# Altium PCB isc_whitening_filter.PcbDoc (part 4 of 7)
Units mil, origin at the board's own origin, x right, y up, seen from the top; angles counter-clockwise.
Board outline 8440 x 7000 mil, 6 copper layers (Top Layer, MidLayer1, InternalPlane1, Internal Plane 3, InternalPlane2, Bottom Layer); 550 components, 434 nets, 2189 pads, 806 vias.
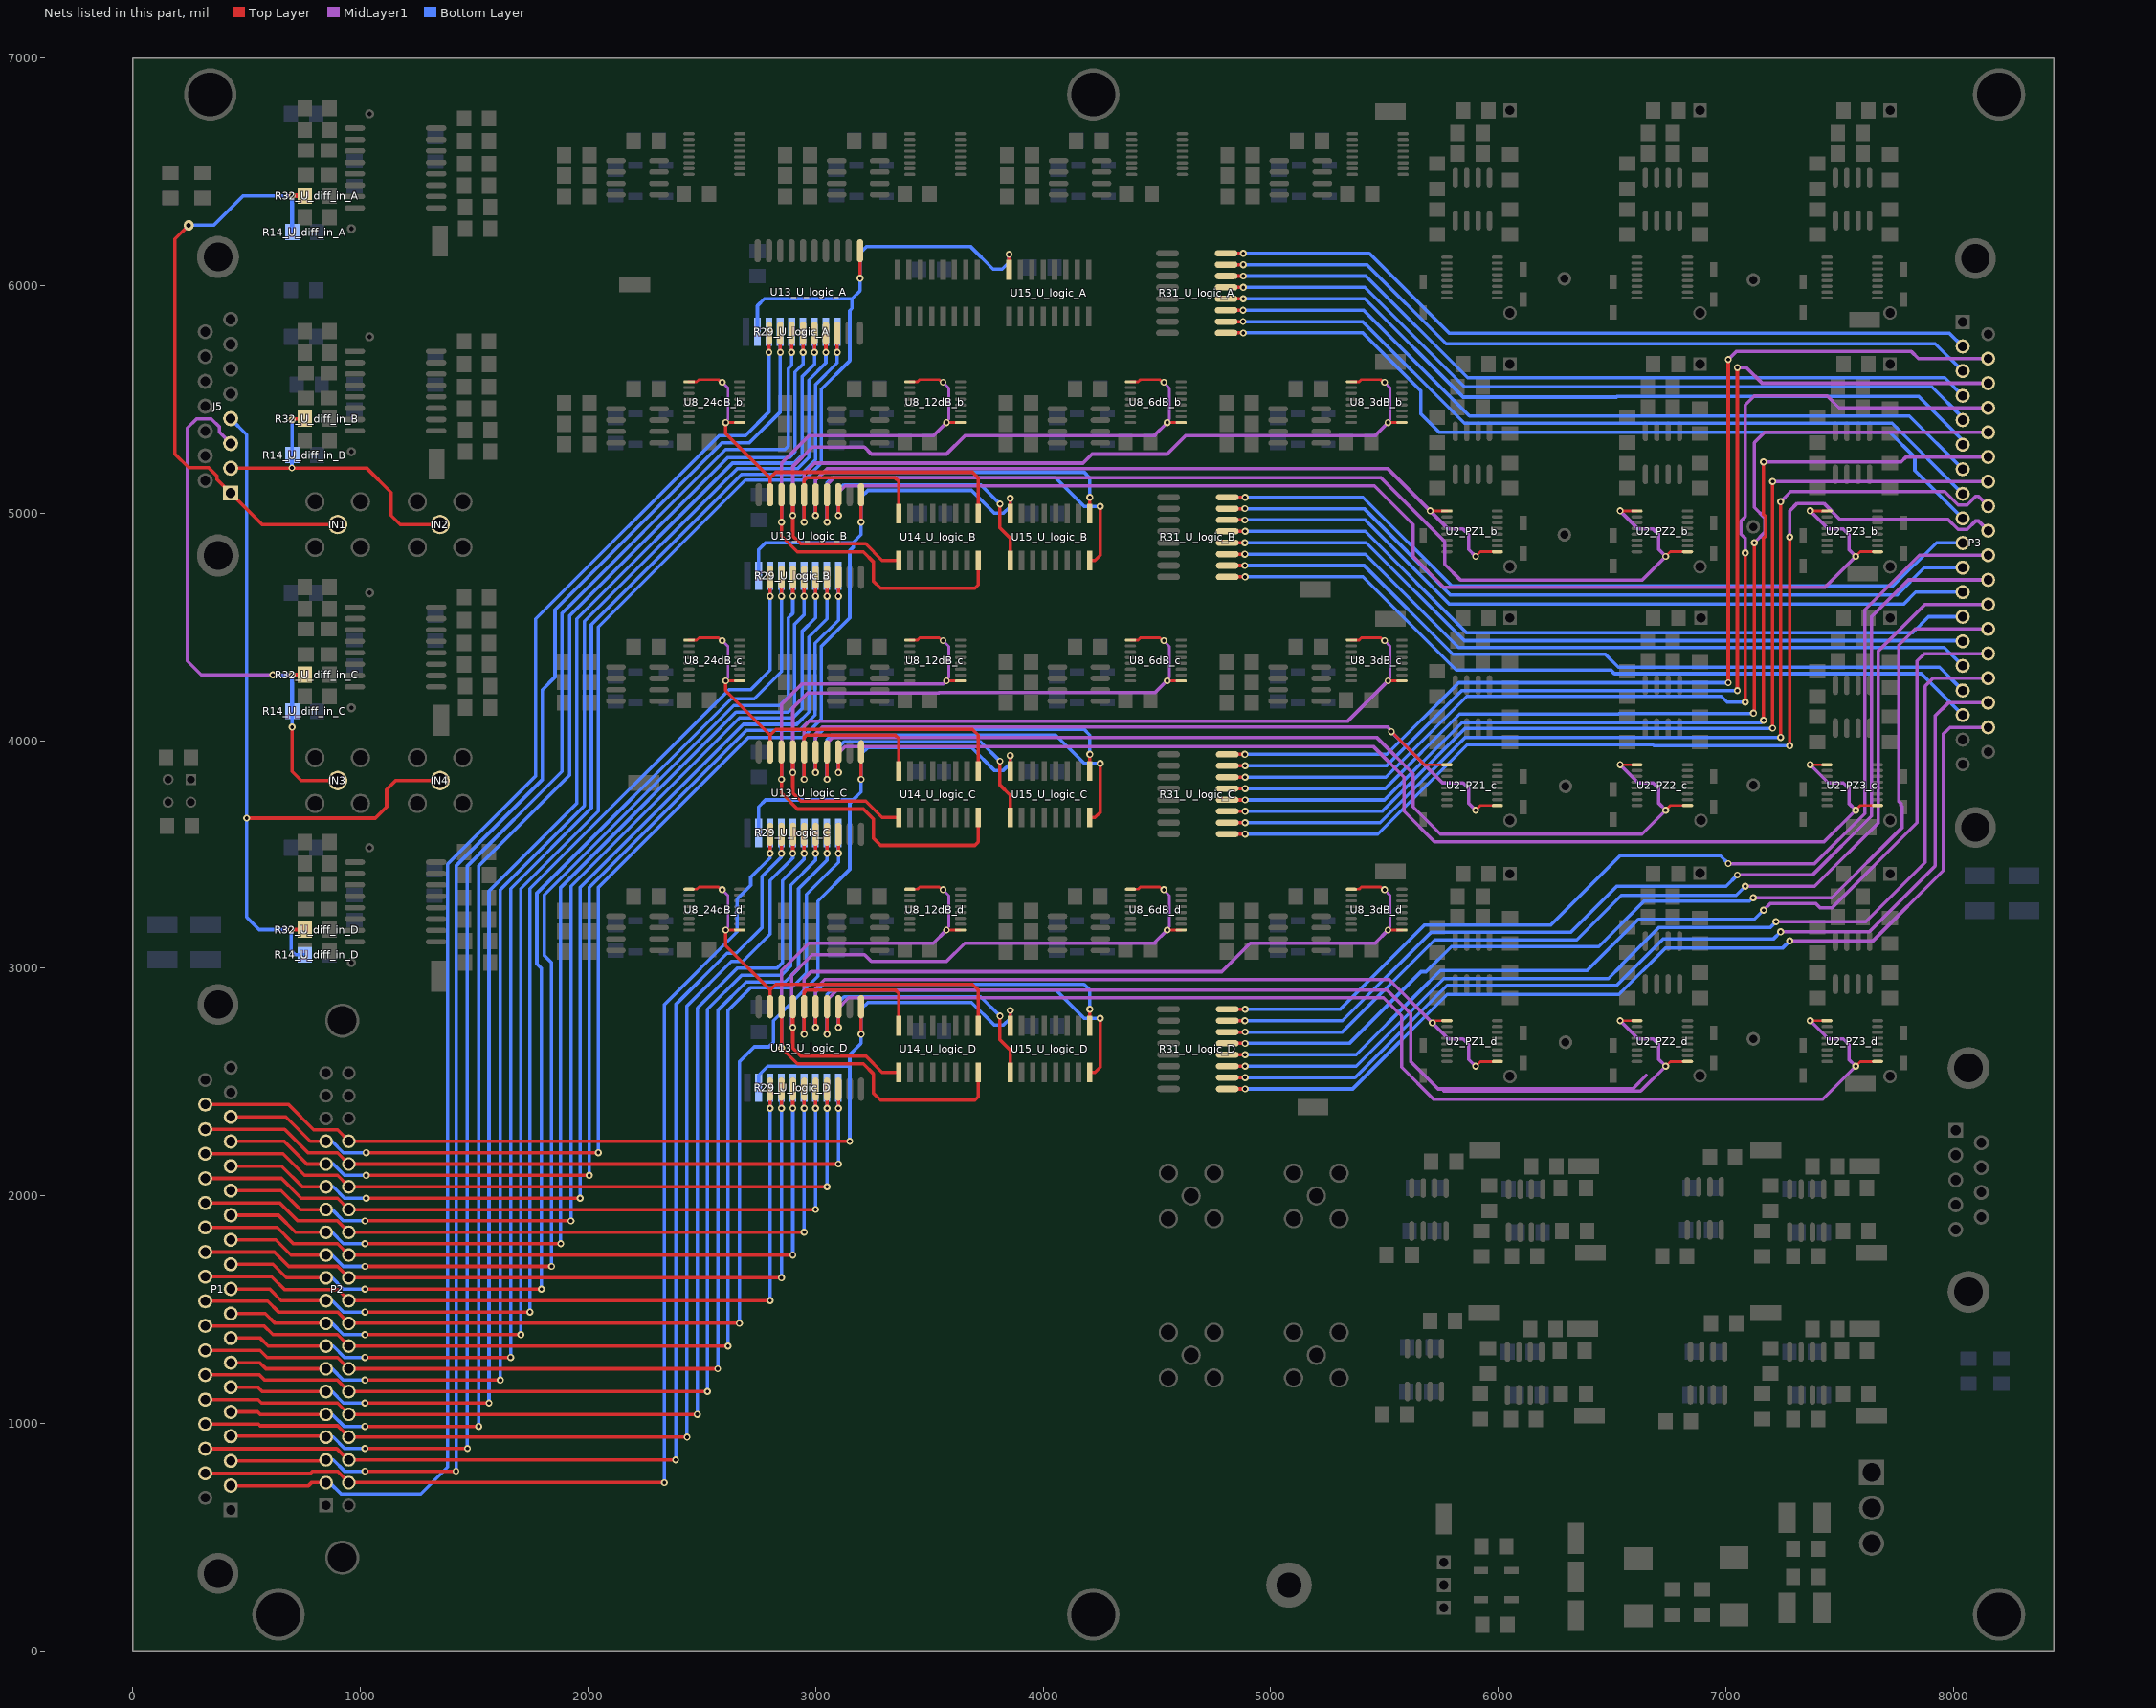
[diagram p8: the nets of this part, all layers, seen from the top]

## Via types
v1: diameter 31, hole 16, Top Layer to Bottom Layer, 805 vias
v2: diameter 45, hole 20, Top Layer to Bottom Layer, 1 vias

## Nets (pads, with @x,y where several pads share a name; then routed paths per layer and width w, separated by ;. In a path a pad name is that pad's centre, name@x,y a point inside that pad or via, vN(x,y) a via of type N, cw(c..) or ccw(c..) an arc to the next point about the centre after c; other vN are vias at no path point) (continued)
AP_1: IN1.1 J5.1 R14_U_diff_in_A.2 R32_U_diff_in_A.2 | length 2605.4
  Top Layer w15: v2(245,6265) 185,6205 185,5260 245,5200 332.74,5200 368.88,5163.86 368.88,5149.35 J5.1@429.92,5088.31 568.23,4950 IN1.1@900,4950
  Top Layer w20: v1(700,6395) R32_U_diff_in_A.2@754.88,6395
  Bottom Layer w15: v2(245,6265) 355,6265 485,6395 v1(700,6395)
  Bottom Layer w20: R14_U_diff_in_A.2@700,6235.12 v1(700,6395)
AP_2: IN2.1 J5.2 R14_U_diff_in_B.2 R32_U_diff_in_B.2 | length 1351
  Top Layer w15: J5.2@429.92,5197.36 697.36,5197.36 v1(698.68,5198.68) 1026.32,5198.68 1135,5090 1135,4990 1175,4950 IN2.1@1350,4950 ; v1(700,5410) 705,5415 R32_U_diff_in_B.2@754.88,5415
  Bottom Layer w15: v1(698.68,5198.68) 698.68,5253.68 700,5255 v1(700,5410)
AP_3: IN3.1 J5.3 R14_U_diff_in_C.2 R32_U_diff_in_C.2 | length 2471.6
  Top Layer w15: v1(700,4060) 700,3865 740,3825 IN3.1@900,3825
  Top Layer w20: v1(700,4290) R32_U_diff_in_C.2@754.88,4290
  MidLayer1 w15: J5.3@429.92,5306.42 380,5356.34 380,5380 345,5415 280,5415 240,5375 240,4350 300,4290 v1(615,4290)
  Bottom Layer w15: v1(615,4290) v1(700,4290) ; R14_U_diff_in_C.2@699.88,4130 700,4129.88 v1(700,4060)
  Bottom Layer w20: R14_U_diff_in_C.2@700,4130.12 v1(700,4290)
AP_4: IN4.1 J5.4 R14_U_diff_in_D.2 R32_U_diff_in_D.2 | length 3617.6
  Top Layer w15: v1(500,3660) 1065,3660 1115,3710 1115,3785 1155,3825 IN4.1@1350,3825 ; v1(695,3170) R32_U_diff_in_D.2@754.88,3170
  Bottom Layer w15: J5.4@429.92,5415.47 500,5345.39 v1(500,3660) 500,3225 555,3170 v1(695,3170) 695,3080 715,3060 R14_U_diff_in_D.2@754.88,3060
B1: U8_24dB_b.1 U8_24dB_b.9 U13_U_logic_B.19 U14_U_logic_B.1 | length 1898.9
  Top Layer w12: U8_24dB_b.9@2443.78,5577.36 2443.95,5577.53 2477.87,5577.53 2487.34,5587 2572.86,5587 2584.86,5575 v1(2590,5575) ; v1(2605,5398.23) U8_24dB_b.1@2666.22,5398.23
  Top Layer w15: v1(2605,5398.23) 2605,5350 2800,5155 ; U13_U_logic_B.19@2800,5081.1 2800,5155 ; U14_U_logic_B.1@3715,4997.36 3715,5155 3690,5180 2825,5180 2800,5155
  MidLayer1 w12: v1(2590,5575) 2615,5550 2615,5413.37 2605,5403.37 v1(2605,5398.23)
B2: U8_12dB_b.1 U8_12dB_b.9 U13_U_logic_B.18 U14_U_logic_B.16 | length 2771.5
  Top Layer w12: U8_12dB_b.9@3413.78,5577.36 3413.95,5577.53 3447.87,5577.53 3457.34,5587 3542.86,5587 3554.86,5575 v1(3560,5575) ; v1(3575,5398.23) U8_12dB_b.1@3636.22,5398.23
  Top Layer w15: U13_U_logic_B.18@2850,5081.1 v1(2850,4960) 2850,4900 2920,4830 3210,4830 3255,4785 3255,4700 3285,4670 3700,4670 3715,4685 U14_U_logic_B.16@3715,4792.64
  MidLayer1 w12: v1(3560,5575) 3585,5550 3585,5413.37 3575,5403.37 v1(3575,5398.23)
  MidLayer1 w15: v1(2850,4960) 2850,5220 2897.5,5267.5 2970,5340 3516.77,5340 v1(3575,5398.23)
B3: U8_6dB_b.1 U8_6dB_b.9 U13_U_logic_B.17 U14_U_logic_B.9 | length 3614.9
  Top Layer w12: U8_6dB_b.9@4383.78,5577.36 4383.95,5577.53 4417.87,5577.53 4427.34,5587 4512.86,5587 4524.86,5575 v1(4530,5575) ; v1(4545,5398.23) U8_6dB_b.1@4606.22,5398.23
  Top Layer w15: U13_U_logic_B.17@2900,5081.1 v1(2900,4990) 2900,4900 2935,4865 3220,4865 3292.36,4792.64 U14_U_logic_B.9@3365,4792.64
  MidLayer1 w12: v1(4530,5575) 4555,5550 4555,5413.37 4545,5403.37 v1(4545,5398.23)
  MidLayer1 w15: v1(2900,4990) 2900,5205 2985,5290 3215,5290 3245,5260 3575,5260 3655,5340 4491.77,5340 ; 3940,5340 4486.77,5340 v1(4545,5398.23)
B4: U8_3dB_b.1 U8_3dB_b.9 U13_U_logic_B.16 U14_U_logic_B.8 | length 4584.9
  Top Layer w12: U8_3dB_b.9@5353.78,5577.36 5353.95,5577.53 5387.87,5577.53 5397.34,5587 5482.86,5587 5494.86,5575 v1(5500,5575) ; v1(5515,5398.23) U8_3dB_b.1@5576.22,5398.23
  Top Layer w15: v1(2950,4960) U13_U_logic_B.16@2950,5081.1 2950,5145 2960,5155 3350,5155 3365,5140 U14_U_logic_B.8@3365,4997.36
  MidLayer1 w12: v1(5500,5575) 5525,5550 5525,5413.37 5515,5403.37 v1(5515,5398.23)
  MidLayer1 w15: v1(2950,4960) 2950,5175 2995,5220 4175,5220 4215,5260 4545,5260 4625,5340 5456.77,5340 ; 4910,5340 5456.77,5340 ; 5461.77,5340 5456.77,5340 ; v1(5515,5398.23) 5456.77,5340
B5: U2_PZ1_b.1 U2_PZ1_b.9 U13_U_logic_B.15 U15_U_logic_B.1 | length 5085.5
  Top Layer w12: v1(5700,5010) 5700.43,5009.57 U2_PZ1_b.1@5773.78,5009.57 ; v1(5900,4810) 5920.43,4830.43 U2_PZ1_b.9@5996.22,4830.43
  Top Layer w15: v1(3000,4990) U13_U_logic_B.15@3000,5081.1 ; U15_U_logic_B.1@4205,4997.36 v1(4205,5070)
  MidLayer1 w15: v1(3000,4990) 3000,5145 3050,5195 5515,5195 v1(5700,5010) 5780,4930 5845,4930 5870,4905 5870,4840 v1(5900,4810)
  Bottom Layer w15: v1(3000,4990) 3000,5145 3035,5180 4180,5180 4205,5155 v1(4205,5070)
B6: U2_PZ2_b.1 U2_PZ2_b.9 U13_U_logic_B.14 U15_U_logic_B.16 | length 6475.9
  Top Layer w12: v1(6535,5010) 6535.43,5009.57 U2_PZ2_b.1@6608.78,5009.57 ; v1(6735,4810) 6755.43,4830.43 U2_PZ2_b.9@6831.22,4830.43
  Top Layer w15: v1(3050,4960) U13_U_logic_B.14@3050,5081.1 ; U15_U_logic_B.16@4205,4792.64 4227.64,4792.64 4250,4815 v1(4250,5030)
  MidLayer1 w15: v1(3050,4960) 3050,5125 3080,5155 5485,5155 5765,4875 5765,4775 5835,4705 6630,4705 v1(6735,4810) 6705,4840 6705,4905 6680,4930 6615,4930 v1(6535,5010)
  Bottom Layer w15: v1(3050,4960) 3050,5135 3070,5155 4055,5155 4180,5030 v1(4250,5030)
B7: U2_PZ3_b.1 U2_PZ3_b.9 U13_U_logic_B.13 U15_U_logic_B.9 | length 6626.9
  Top Layer w12: v1(7370,5010) 7370.43,5009.57 U2_PZ3_b.1@7443.78,5009.57 ; v1(7570,4810) 7590.43,4830.43 U2_PZ3_b.9@7666.22,4830.43
  Top Layer w15: v1(3100,4990) U13_U_logic_B.13@3100,5081.1 ; v1(3810,5040) 3810,4935 3855,4890 U15_U_logic_B.9@3855,4792.64
  MidLayer1 w15: v1(3100,4990) 3100,5090 3130,5120 5455,5120 5625,4950 5625,4810 5760,4675 7380,4675 7435,4675 v1(7570,4810) 7540,4840 7540,4905 7515,4930 7450,4930 v1(7370,5010)
  Bottom Layer w15: v1(3100,4990) 3100,5100 3125,5125 3725,5125 v1(3810,5040)
BI_0: P1.2 P2.3 R29_U_logic_A.3 U13_U_logic_A.2 | length 6752.5
  Top Layer w15: P1.2@430,727 772,727 785,740 P2.3@849,740 ; v1(2795,5707) U13_U_logic_A.2@2795,5790.9
  Bottom Layer w15: P2.3@849,740 865,740 915,690 1265,690 1382.93,807.93 1382.93,3457.93 1770,3845 1770,4535 2575,5340 2690,5340 2795,5445 v1(2795,5707) ; v1@2794.41,5707.59 R29_U_logic_A.3@2794.41,5797
BI_1: P1.3 P2.5 R29_U_logic_A.4 U13_U_logic_A.3 | length 6763.6
  Top Layer w15: P1.3@430,835 844,835 P2.5@849,840 ; v1(1020,790) v1(1420,790) ; v1(2845,5707) U13_U_logic_A.3@2845,5790.9
  Bottom Layer w15: P2.5@849,840 880,840 930,790 v1(1020,790) ; v1(1420,790) 1420,3450 1800,3830 1800,4225 1855,4280 1855,4575 2590,5310 2710,5310 2845,5445 v1(2845,5707) ; v1@2844.41,5707.59 R29_U_logic_A.4@2844.41,5797
BI_2: P1.4 P2.7 R29_U_logic_A.5 U13_U_logic_A.4 | length 6795.2
  Top Layer w15: P1.4@430,944 845,944 P2.7@849,940 ; v1(1020,890) v1(1470,890) ; v1(2895,5707) U13_U_logic_A.4@2895,5790.9
  Bottom Layer w15: P2.7@849,940 880,940 930,890 v1(1020,890) ; v1(1470,890) 1470,3450 1885,3865 1885,4560 2605,5280 2865,5280 2880,5295 2880,5635 2895,5650 v1(2895,5707) ; v1@2894.41,5707.59 R29_U_logic_A.5@2894.41,5797
BI_3: P1.5 P2.9 R29_U_logic_A.6 U13_U_logic_A.5 | length 6757.5
  Top Layer w15: P1.5@430,1051 549,1051 560,1040 P2.9@849,1040 ; v1(1020,987.5) v1(1520,987.5) ; v1(2945,5707) U13_U_logic_A.5@2945,5790.9
  Bottom Layer w15: P2.9@849,1040 875,1040 927.5,987.5 v1(1020,987.5) ; v1(1520,987.5) 1520,3450 1920,3850 1920,4550 2615,5245 2885,5245 2910,5270 2910,5620 2945,5655 v1(2945,5707) ; v1@2944.41,5707.59 R29_U_logic_A.6@2944.41,5797
BI_4: P1.6 P2.11 R29_U_logic_A.7 U13_U_logic_A.6 | length 6704.4
  Top Layer w15: P1.6@430,1159 549,1159 568,1140 P2.11@849,1140 ; v1(1020,1090) v1(1565,1090) ; v1(2995,5707) U13_U_logic_A.6@2995,5790.9
  Bottom Layer w15: P2.11@849,1140 875,1140 925,1090 v1(1020,1090) ; v1(1565,1090) 1565,3340 1950,3725 1950,4535 2635,5220 2905,5220 2940,5255 2940,5600 2995,5655 v1(2995,5707) ; v1@2994.41,5707.59 R29_U_logic_A.7@2994.41,5797
BI_5: P1.7 P2.13 R29_U_logic_A.8 U13_U_logic_A.7 | length 6654.8
  Top Layer w15: P1.7@430,1267 558,1267 585,1240 P2.13@849,1240 ; v1(1020,1190) v1(1615,1190) ; v1(3045,5707) U13_U_logic_A.7@3045,5790.9
  Bottom Layer w15: P2.13@849,1240 875,1240 925,1190 v1(1020,1190) ; v1(1615,1190) 1615,3345 1984.82,3714.82 1984.82,4524.82 2655,5195 2920,5195 2970,5245 2970,5585 3045,5660 v1(3045,5707) ; v1@3044.41,5707.59 R29_U_logic_A.8@3044.41,5797
BI_6: P1.8 P2.15 R29_U_logic_A.9 U13_U_logic_A.8 | length 6602.2
  Top Layer w15: P1.8@430,1375 560,1375 595,1340 P2.15@849,1340 ; v1(1020,1290) v1(1660,1290) ; v1(3095,5707) U13_U_logic_A.8@3095,5790.9
  Bottom Layer w15: P2.15@849,1340 880,1340 930,1290 v1(1020,1290) ; v1(1660,1290) 1660,3350 2014.82,3704.82 2014.82,4509.82 2675,5170 2935,5170 3000,5235 3000,5565 3095,5660 v1(3095,5707) ; v1@3094.41,5707.59 R29_U_logic_A.9@3094.41,5797
BI_7: P1.9 P2.17 R29_U_logic_A.2 U13_U_logic_A.11 U15_U_logic_A.8 | length 8322.7
  Top Layer w15: P1.9@430,1483 582,1483 625,1440 P2.17@849,1440 ; v1(1020,1390) v1(1705,1390) ; v1(3195,6032) U13_U_logic_A.11@3195,6153.1 ; U15_U_logic_A.8@3850,6069.36 v1(3850,6137)
  Bottom Layer w15: P2.17@849,1440 875,1440 925,1390 v1(1020,1390) ; v1(1705,1390) 1705,3350 2045,3690 2045,4500 2690,5145 2950,5145 3025,5220 3025,5545 3150,5670 3150,5890 3160,5900 3160,5942 ; R29_U_logic_A.2@2744.41,5797 2744.41,5911.41 2775,5942 3160,5942 ; v1(3850,6137) 3850,6102 3820,6072 3780,6072 3680,6172 3225,6172 3195,6142 v1(3195,6032) 3195,5977 3160,5942
BI_8: P1.10 P2.19 R29_U_logic_B.3 U13_U_logic_B.2 | length 5167.8
  Top Layer w15: P1.10@430,1591 601,1591 652,1540 P2.19@849,1540 ; v1(1020,1490) v1(1745,1490) ; v1(2800,4635) U13_U_logic_B.2@2800,4718.9
  Bottom Layer w15: P2.19@849,1540 875,1540 925,1490 v1(1020,1490) ; v1(1745,1490) 1745,3350 2620,4225 2715,4225 2800,4310 v1(2800,4635) ; v1@2799.41,4635.59 R29_U_logic_B.3@2799.41,4725
BI_9: P1.11 P2.21 R29_U_logic_B.4 U13_U_logic_B.3 | length 5140.6
  Top Layer w15: P1.11@430,1699 616,1699 675,1640 P2.21@849,1640 ; v1(1020,1590) v1(1795,1590) ; v1(2850,4635) U13_U_logic_B.3@2850,4718.9
  Bottom Layer w15: P2.21@849,1640 875,1640 925,1590 v1(1020,1590) ; v1(1795,1590) 1795,3000 1775,3020 1775,3330 2630,4185 2730,4185 2850,4305 v1(2850,4635) ; v1@2849.41,4635.59 R29_U_logic_B.4@2849.41,4725
BI_10: P1.12 P2.23 R29_U_logic_B.5 U13_U_logic_B.4 | length 5162.1
  Top Layer w15: P1.12@430,1807 628,1807 695,1740 P2.23@849,1740 ; v1(1020,1690) v1(1840,1690) ; v1(2900,4635) U13_U_logic_B.4@2900,4718.9
  Bottom Layer w15: P2.23@849,1740 875,1740 925,1690 v1(1020,1690) ; v1(1840,1690) 1840,3023.33 1807,3056.33 1807,3322 2640,4155 2843,4155 2880,4192 2880,4540 2900,4560 v1(2900,4635) ; v1@2899.41,4635.59 R29_U_logic_B.5@2899.41,4725
BI_11: P1.13 P2.25 R29_U_logic_B.6 U13_U_logic_B.5 | length 5098
  Top Layer w15: P1.13@430,1915 640,1915 715,1840 P2.25@849,1840 ; v1(1020,1790) v1(1880,1790) ; v1(2950,4635) U13_U_logic_B.5@2950,4718.9
  Bottom Layer w15: P2.25@849,1840 875,1840 925,1790 v1(1020,1790) ; v1(1880,1790) 1880,3355 2650,4125 2880,4125 2908,4153 2908,4513 2950,4555 v1(2950,4635) ; v1@2949.41,4635.59 R29_U_logic_B.6@2949.41,4725
BI_12: P1.14 P2.27 R29_U_logic_B.7 U13_U_logic_B.6 | length 5051.3
  Top Layer w15: P1.14@430,2023 652,2023 735,1940 P2.27@849,1940 ; v1(1020,1890) v1(1925,1890) ; v1(3000,4635) U13_U_logic_B.6@3000,4718.9
  Bottom Layer w15: P2.27@849,1940 875,1940 925,1890 v1(1020,1890) ; v1(1925,1890) 1925,3360 2665,4100 2900,4100 2940,4140 2940,4480 3000,4540 v1(3000,4635) ; v1@2999.41,4635.59 R29_U_logic_B.7@2999.41,4725
BI_13: P1.15 P2.29 R29_U_logic_B.8 U13_U_logic_B.7 | length 4998.8
  Top Layer w15: P1.15@430,2131 654,2131 745,2040 P2.29@849,2040 ; v1(1025,1990) v1(1965,1990) ; v1(3050,4635) U13_U_logic_B.7@3050,4718.9
  Bottom Layer w15: P2.29@849,2040 880,2040 930,1990 v1(1025,1990) ; v1(1965,1990) 1965,3355 2682,4072 2917,4072 2971,4126 2971,4456 3050,4535 v1(3050,4635) ; v1@3049.41,4635.59 R29_U_logic_B.8@3049.41,4725
BI_14: P1.16 P2.31 R29_U_logic_B.9 U13_U_logic_B.8 | length 4951
  Top Layer w15: P1.16@430,2239 666,2239 765,2140 P2.31@849,2140 ; v1(1025,2090) v1(2005,2090) ; v1(3100,4635) U13_U_logic_B.8@3100,4718.9
  Bottom Layer w15: P2.31@849,2140 880,2140 930,2090 v1(1025,2090) ; v1@2005,2085 2005,3355 2695,4045 2929.64,4045 2998,4113.36 2998,4428 3100,4530 v1(3100,4635) ; v1@3099.41,4635.59 R29_U_logic_B.9@3099.41,4725
BI_15: P1.17 P2.33 R29_U_logic_B.2 U13_U_logic_B.11 U15_U_logic_B.8 | length 6666.7
  Top Layer w15: P1.17@430,2347 673,2347 780,2240 P2.33@849,2240 ; v1(1025,2190) v1(2045,2190) ; v1(3200,4960) U13_U_logic_B.11@3200,5081.1 ; U15_U_logic_B.8@3855,4997.36 v1(3855,5065)
  Bottom Layer w15: P2.33@849,2240 875,2240 925,2190 v1(1025,2190) ; v1(2045,2190) 2045,3355 2705,4015 2945,4015 3025,4095 3025,4415 3150,4540 3150,4835 3165,4850 3165,4870 ; R29_U_logic_B.2@2749.41,4725 2749.41,4839.41 2780,4870 3165,4870 ; v1(3855,5065) 3855,5030 3825,5000 3785,5000 3685,5100 3230,5100 3200,5070 v1(3200,4960) 3200,4905 3165,4870
BI_16: P1.21 P2.4 R29_U_logic_C.3 U13_U_logic_C.2 | length 5172.4
  Top Layer w15: P1.21@318,781 781,781 790,790 899,790 P2.4@949,740 v1(2335,740) ; v1(2800,3505) U13_U_logic_C.2@2800,3588.9
  Bottom Layer w15: v1(2335,740) 2335,2840 2655,3160 2655,3305 2715,3365 2715,3400 2800,3485 v1(2800,3505) ; v1@2799.41,3505.59 R29_U_logic_C.3@2799.41,3595
BI_17: P1.22 P2.6 R29_U_logic_C.4 U13_U_logic_C.3 | length 5141.6
  Top Layer w15: P1.22@318,889 896,889 945,840 P2.6@949,840 v1(2385,840) ; v1(2850,3505) U13_U_logic_C.3@2850,3588.9
  Bottom Layer w15: v1(2385,840) 2385,2840 2611.33,3066.33 2651.33,3066.33 2765,3180 2765,3405 2850,3490 v1(2850,3505) ; v1@2849.41,3505.59 R29_U_logic_C.4@2849.41,3595
BI_18: P1.23 P2.8 R29_U_logic_C.5 U13_U_logic_C.4 | length 5100.8
  Top Layer w15: P1.23@318,997 553,997 560,990 899,990 P2.8@949,940 v1(2435,940) ; v1(2900,3505) U13_U_logic_C.4@2900,3588.9
  Bottom Layer w15: v1(2435,940) 2435,2835 2630,3030 2680,3030 2800,3150 2800,3385 2900,3485 v1(2900,3505) ; v1@2899.41,3505.59 R29_U_logic_C.5@2899.41,3595
BI_19: P1.24 P2.10 R29_U_logic_C.6 U13_U_logic_C.5 | length 5125
  Top Layer w15: P1.24@318,1105 550,1105 565,1090 900,1090 949,1041 P2.10@949,1040 v1(2480,1040) ; v1(2950,3505) U13_U_logic_C.5@2950,3588.9
  Bottom Layer w15: v1(2480,1040) 2480,2825 2655,3000 2830,3000 2855,3025 2855,3385 2950,3480 v1(2950,3505) ; v1@2949.41,3505.59 R29_U_logic_C.6@2949.41,3595
BI_20: P1.25 P2.12 R29_U_logic_C.7 U13_U_logic_C.6 | length 5074.8
  Top Layer w15: P1.25@318,1213 557,1213 580,1190 899,1190 P2.12@949,1140 v1(2525,1140) ; v1(3000,3505) U13_U_logic_C.6@3000,3588.9
  Bottom Layer w15: v1(2525,1140) 2525,2820 2675,2970 2850,2970 2890,3010 2890,3365 3000,3475 v1(3000,3505) ; v1@2999.41,3505.59 R29_U_logic_C.7@2999.41,3595
BI_21: P1.26 P2.14 R29_U_logic_C.8 U13_U_logic_C.7 | length 5022.3
  Top Layer w15: P1.26@318,1321 559,1321 590,1290 899,1290 P2.14@949,1240 v1(2570,1240) ; v1(3050,3505) U13_U_logic_C.7@3050,3588.9
  Bottom Layer w15: v1(2570,1240) 2570,2815 2695,2940 2865,2940 2925,3000 2925,3350 3050,3475 v1(3050,3505) ; v1@3049.41,3505.59 R29_U_logic_C.8@3049.41,3595
BI_22: P1.27 P2.16 R29_U_logic_C.9 U13_U_logic_C.8 | length 4978.5
  Top Layer w15: P1.27@318,1429 576,1429 615,1390 899,1390 P2.16@949,1340 v1(2615,1340) ; v1(3100,3505) U13_U_logic_C.8@3100,3588.9
  Bottom Layer w15: v1(2615,1340) 2615,2815 2715,2915 2895,2915 2960,2980 2960,3325 3100,3465 v1(3100,3505) ; v1@3099.41,3505.59 R29_U_logic_C.9@3099.41,3595
BI_23: P1.28 P2.18 R29_U_logic_C.2 U13_U_logic_C.11 U15_U_logic_C.8 | length 6634.5
  Top Layer w15: P1.28@318,1537 593,1537 640,1490 899,1490 P2.18@949,1440 v1(2665,1440) ; v1(3200,3830) U13_U_logic_C.11@3200,3951.1 ; U15_U_logic_C.8@3855,3867.36 v1(3855,3935)
  Bottom Layer w15: v1(2665,1440) 2665,2590 2730,2655 2795,2655 2815,2675 2815,2770 2955,2910 3010,2965 3010,3295 3150,3435 3150,3725 3165,3740 ; R29_U_logic_C.2@2749.41,3595 2749.41,3709.41 2780,3740 3165,3740 ; v1(3855,3935) 3855,3900 3825,3870 3785,3870 3685,3970 3230,3970 3200,3940 v1(3200,3830) 3200,3775 3165,3740
BI_24: P1.29 P2.20 R29_U_logic_D.3 U13_U_logic_D.2 | length 3543.8
  Top Layer w15: P1.29@318,1645 610,1645 667,1588 901,1588 P2.20@949,1540 v1(2800,1540) ; v1(2800,2385) U13_U_logic_D.2@2800,2468.9
  Bottom Layer w15: v1@2799.41,2385.59 R29_U_logic_D.3@2799.41,2475 ; v1(2800,1540) v1(2800,2385)
BI_25: P1.30 P2.22 R29_U_logic_D.4 U13_U_logic_D.3 | length 3497.1
  Top Layer w15: P1.30@318,1753 622,1753 685,1690 899,1690 P2.22@949,1640 v1(2850,1640) ; v1(2850,2385) U13_U_logic_D.3@2850,2468.9
  Bottom Layer w15: v1@2849.41,2385.59 R29_U_logic_D.4@2849.41,2475 ; v1(2850,1640) v1(2850,2385)
BI_26: P1.31 P2.24 R29_U_logic_D.5 U13_U_logic_D.4 | length 3450.4
  Top Layer w15: P1.31@318,1861 634,1861 705,1790 899,1790 P2.24@949,1740 v1(2900,1740) ; v1(2900,2385) U13_U_logic_D.4@2900,2468.9
  Bottom Layer w15: v1@2899.41,2385.59 R29_U_logic_D.5@2899.41,2475 ; v1(2900,1740) v1(2900,2385)
BI_27: P1.32 P2.26 R29_U_logic_D.6 U13_U_logic_D.5 | length 3403.7
  Top Layer w15: P1.32@318,1969 646,1969 725,1890 899,1890 P2.26@949,1840 v1(2950,1840) ; v1(2950,2385) U13_U_logic_D.5@2950,2468.9
  Bottom Layer w15: v1@2949.41,2385.59 R29_U_logic_D.6@2949.41,2475 ; v1(2950,1840) v1(2950,2385)
BI_28: P1.33 P2.28 R29_U_logic_D.7 U13_U_logic_D.6 | length 3357.1
  Top Layer w15: P1.33@318,2077 653,2077 740,1990 899,1990 P2.28@949,1940 v1(3000,1940) ; v1(3000,2385) U13_U_logic_D.6@3000,2468.9
  Bottom Layer w15: v1@2999.41,2385.59 R29_U_logic_D.7@2999.41,2475 ; v1(3000,1940) v1(3000,2385)
BI_29: P1.34 P2.30 R29_U_logic_D.8 U13_U_logic_D.7 | length 3310.4
  Top Layer w15: P1.34@318,2185 660,2185 755,2090 899,2090 P2.30@949,2040 v1(3050,2040) ; v1(3050,2385) U13_U_logic_D.7@3050,2468.9
  Bottom Layer w15: v1@3049.41,2385.59 R29_U_logic_D.8@3049.41,2475 ; v1(3050,2040) v1(3050,2385)
BI_30: P1.35 P2.32 R29_U_logic_D.9 U13_U_logic_D.8 | length 3263.7
  Top Layer w15: P1.35@318,2293 667,2293 770,2190 899,2190 P2.32@949,2140 v1(3100,2140) ; v1(3100,2385) U13_U_logic_D.8@3100,2468.9
  Bottom Layer w15: v1@3099.41,2385.59 R29_U_logic_D.9@3099.41,2475 ; v1(3100,2140) v1(3100,2385)
BI_31: P1.36 P2.34 R29_U_logic_D.2 U13_U_logic_D.11 U15_U_logic_D.8 | length 4916.2
  Top Layer w15: P1.36@318,2401 684,2401 795,2290 899,2290 P2.34@949,2240 v1(3150,2240) ; v1(3200,2710) U13_U_logic_D.11@3200,2831.1 ; U15_U_logic_D.8@3855,2747.36 v1(3855,2815)
  Bottom Layer w15: R29_U_logic_D.2@2749.41,2475 2749.41,2529.41 2790,2570 3150,2570 ; v1(3150,2240) 3150,2620 3200,2670 v1(3200,2710) 3200,2820 3230,2850 3685,2850 3785,2750 3825,2750 3855,2780 v1(3855,2815)
BO_0: P3.2 R31_U_logic_A.16 | length 3405.5
  Top Layer w15: R31_U_logic_A.16@4803.94,6142 v1(4879,6142)
  Bottom Layer w15: v1(4879,6142) 5433,6142 5785,5790 7983,5790 P3.2@8040,5733
BO_1: P3.3 R31_U_logic_A.15 | length 3429.5
  Top Layer w15: R31_U_logic_A.15@4803.94,6092 v1(4879,6092)
  Bottom Layer w15: v1(4879,6092) 5423,6092 5770,5745 7920,5745 P3.3@8040,5625
BO_2: P3.4 R31_U_logic_A.14 | length 3453.9
  Top Layer w15: R31_U_logic_A.14@4803.94,6042 v1(4879,6042)
  Bottom Layer w15: v1(4879,6042) 5418,6042 5865,5595 7961,5595 P3.4@8040,5516
BO_3: P3.5 R31_U_logic_A.13 | length 3484
  Top Layer w15: R31_U_logic_A.13@4803.94,5992 v1(4879,5992)
  Bottom Layer w15: v1(4879,5992) 5413,5992 5850,5555 7905,5555 8040,5420 P3.5@8040,5409
BO_4: P3.6 R31_U_logic_A.12 | length 3515.2
  Top Layer w15: R31_U_logic_A.12@4803.94,5942 v1(4879,5942)
  Bottom Layer w15: v1(4879,5942) 5413,5942 5845,5510 6518.33,5510 6521.33,5513 7847,5513 8040,5320 P3.6@8040,5301
BO_5: P3.7 R31_U_logic_A.11 | length 3525.6
  Top Layer w15: R31_U_logic_A.11@4803.94,5892 v1(4878,5892)
  Bottom Layer w15: v1(4878,5892) 5408,5892 5873,5427 7806,5427 P3.7@8040,5193
BO_6: P3.8 R31_U_logic_A.10 | length 3582.1
  Top Layer w15: R31_U_logic_A.10@4771.46,5842 v1(4878,5842)
  Bottom Layer w15: v1(4878,5842) 5403,5842 5850,5395 7730,5395 P3.8@8040,5085
BO_7: P3.9 R31_U_logic_A.9 | length 3667.2
  Top Layer w15: R31_U_logic_A.9@4803.94,5792 v1(4879,5792)
  Bottom Layer w15: v1(4879,5792) 5404.67,5792 5660,5536.67 5660,5435 5740,5355 7720,5355 7830,5245 7830,5187 P3.9@8040,4977
BO_8: P3.10 R31_U_logic_B.16 | length 3504.2
  Top Layer w15: R31_U_logic_B.16@4776.46,5070 v1(4887,5070)
  Bottom Layer w15: v1(4887,5070) 5405,5070 5795,4680 7735,4680 7925,4870 8039,4870 P3.10@8040,4869
BO_9: P3.11 R31_U_logic_B.15 | length 3471.1
  Top Layer w15: R31_U_logic_B.15@4776.46,5020 v1(4886,5020)
  Bottom Layer w15: v1(4886,5020) 5410,5020 5790,4640 7750,4640 7871,4761 P3.11@8040,4761
BO_10: P3.12 R31_U_logic_B.14 | length 3438.8
  Top Layer w15: R31_U_logic_B.14@4776.46,4970 v1(4886,4970)
  Bottom Layer w15: v1(4886,4970) 5415,4970 5785,4600 7780,4600 7833,4653 P3.12@8040,4653
BO_11: P3.13 R31_U_logic_B.13 | length 3476.9
  Top Layer w15: R31_U_logic_B.13@4776.46,4920 v1(4887,4920)
  Bottom Layer w15: v1(4887,4920) 5415,4920 5860,4475 7820,4475 7890,4545 P3.13@8040,4545
BO_12: P3.14 R31_U_logic_B.12 | length 3442.9
  Top Layer w15: R31_U_logic_B.12@4776.46,4870 v1(4886,4870)
  Bottom Layer w15: v1(4886,4870) 5420,4870 5850,4440 8037,4440 P3.14@8040,4437
BO_13: P3.15 R31_U_logic_B.11 | length 3466.9
  Top Layer w15: R31_U_logic_B.11@4776.46,4820 v1(4886,4820)
  Bottom Layer w15: v1(4886,4820) 5415,4820 5825,4410 7959,4410 P3.15@8040,4329
BO_14: P3.16 R31_U_logic_B.10 | length 3504.9
  Top Layer w15: R31_U_logic_B.10@4776.46,4770 v1(4886,4770)
  Bottom Layer w15: v1(4886,4770) 5410,4770 5800,4380 6470,4380 6527,4323 7915,4323 7938,4323 P3.16@8040,4221 P3.16@8040,4235
BO_15: P3.17 R31_U_logic_B.9 | length 3515
  Top Layer w15: R31_U_logic_B.9@4776.46,4720 v1(4887,4720)
  Bottom Layer w15: v1(4887,4720) 5405,4720 5815,4310 6495,4310 6510,4295 7858,4295 P3.17@8040,4113
BO_16: P3.21 R31_U_logic_C.16 | length 4953.4
  Top Layer w15: R31_U_logic_C.16@4776.46,3940 R31_U_logic_C.16@4808.94,3940 v1(4886,3940) ; v1(7010,4255) v1(7010,5675)
  MidLayer1 w15: v1(7010,5675) 7045,5710 7815,5710 7846,5679 P3.21@8152,5679
  Bottom Layer w15: v1(4886,3940) 5510.67,3940 5825.67,4255 v1(7010,4255)
BO_17: P3.22 R31_U_logic_C.15 | length 4960.8
  Top Layer w15: R31_U_logic_C.15@4776.46,3890 v1(4887,3890) ; v1(7050,4220) v1(7050,5640)
  MidLayer1 w15: v1(7050,5640) 7090,5640 7159,5571 P3.22@8152,5571
  Bottom Layer w15: v1(4887,3890) 5509,3890 5839,4220 v1(7050,4220)
BO_18: P3.23 R31_U_logic_C.14 | length 4892.8
  Top Layer w15: R31_U_logic_C.14@4776.46,3840 v1(4887,3840) ; v1(7085,4170) v1(7085,4825)
  MidLayer1 w15: v1(7085,4825) 7085,4890 ; 7085,4889 7066,4908 7066,4965.68 7085,4984.68 7085,5475 7125,5515 7445,5515 7497,5463 P3.23@8152,5463
  Bottom Layer w15: v1(4887,3840) 5506,3840 5861,4195 6980,4195 7005,4170 v1(7085,4170)
BO_19: P3.24 R31_U_logic_C.13 | length 4765.2
  Top Layer w15: R31_U_logic_C.13@4776.46,3790 v1(4887,3790) ; v1@7120,4870 v1(7125,4870) 7125,4125 v1(7121,4121)
  MidLayer1 w15: v1@7120,4870 v1(7125,4870) 7170,4915 7170,4980 7125,5025 7125,5310 7170,5355 P3.24@8152,5355
  Bottom Layer w15: v1(4887,3790) 5503,3790 5830,4117 6527.67,4117 6530.67,4120 7120,4120 v1(7121,4121)
BO_20: P3.25 R31_U_logic_C.12 | length 4672.9
  Top Layer w15: R31_U_logic_C.12@4776.46,3740 v1(4887,3740) ; v1(7165,4090) 7165,4890 7175,4900 7175,4985 7165,4995 v1(7165,5225)
  MidLayer1 w15: v1(7165,5225) 7770,5225 7792,5247 P3.25@8152,5247
  Bottom Layer w15: v1(4887,3740) 5500,3740 5840,4080 7155,4080 v1(7165,4090)
BO_21: P3.26 R31_U_logic_C.11 | length 4610.7
  Top Layer w15: R31_U_logic_C.11@4776.46,3690 v1(4887,3690) ; v1(7205,4055) v1(7205,5139)
  MidLayer1 w15: v1(7205,5139) P3.26@8152,5139
  Bottom Layer w15: v1(4887,3690) 5490,3690 5855,4055 v1(7205,4055)
BO_22: P3.27 R31_U_logic_C.10 | length 4641.7
  Top Layer w15: R31_U_logic_C.10@4776.46,3640 v1(4887,3640) ; v1(7240,4015) v1(7240,5050)
  MidLayer1 w15: v1(7240,5050) 7285,5095 7961.41,5095 8019.91,5036.5 8060.09,5036.5 8097.08,5073.49 8109.51,5073.49 P3.27@8152,5031
  Bottom Layer w15: v1(4887,3640) 5480,3640 5855,4015 v1(7240,4015)
BO_23: P3.28 R31_U_logic_C.9 | length 4666.4
  Top Layer w15: R31_U_logic_C.9@4776.46,3590 v1(4887,3590) ; v1(7280,3978) v1(7280,4895)
  MidLayer1 w15: v1(7280,4895) 7280,5010 7313,5043 7430.33,5043 7501.33,4972 7976.41,4972 8019.91,4928.5 8060.09,4928.5 8097.08,4965.49 8109.51,4965.49 P3.28@8152,4923
  Bottom Layer w15: v1(4887,3590) 5470,3590 5863,3983 6678.67,3983 6683.67,3978 v1(7280,3978)
BO_24: P3.29 R31_U_logic_D.16 | length 4755.2
  Top Layer w15: R31_U_logic_D.16@4776.46,2820 R31_U_logic_D.16@4808.94,2820 v1(4887,2820)
  MidLayer1 w15: v1(7010,3460) 7390,3460 7610,3680 7610,4575 7850,4815 P3.29@8152,4815
  Bottom Layer w15: v1(4887,2820) 5305,2820 5675,3190 6230,3190 6535,3495 6975,3495 v1(7010,3460)
BO_25: P3.30 R31_U_logic_D.15 | length 4690.4
  Top Layer w15: R31_U_logic_D.15@4776.46,2770 v1(4886,2770)
  MidLayer1 w15: v1(7050,3410) 7060,3410 7380,3410 7640,3670 7640,4545 7802,4707 P3.30@8152,4707
  Bottom Layer w15: v1(4886,2770) 5315,2770 5702.82,3157.82 6317.82,3157.82 6520,3360 7000,3360 v1(7050,3410)
BO_26: P3.31 R31_U_logic_D.14 | length 4596.1
  Top Layer w15: R31_U_logic_D.14@4776.46,2720 v1(4887,2720)
  MidLayer1 w15: v1(7085,3360) 7390,3360 7670,3640 7670,4395 7795,4520 7874,4599 P3.31@8152,4599
  Bottom Layer w15: v1(4887,2720) 5315,2720 5670,3075 5720,3125 5780,3125 6345,3125 6540,3320 7045,3320 v1(7085,3360)
BO_27: P3.32 R31_U_logic_D.13 | length 4619.7
  Top Layer w15: R31_U_logic_D.13@4776.46,2670 v1(4887,2670)
  MidLayer1 w15: v1(7120,3310) 7465,3310 7775,3620 7775,3710 7769,3716 7769,3724.67 7760,3733.67 7760,4420 7831,4491 P3.32@8152,4491
  Bottom Layer w15: v1(4887,2670) 5345,2670 5660,2985 5683,2985 5793.74,3095.74 6440.74,3095.74 6640,3295 7103.21,3295 7118.21,3310 v1(7120,3310)
BO_28: P3.33 R31_U_logic_D.12 | length 4538.3
  Top Layer w15: R31_U_logic_D.12@4776.46,2620 v1(4887,2620)
  MidLayer1 w15: v1(7165,3255) 7195,3285 7395,3285 7415,3265 7465,3265 7840,3640 7840,4350 7873,4383 P3.33@8152,4383
  Bottom Layer w15: v1(4887,2620) 5375,2620 5650,2895 5745,2990 6390,2990 6615,3215 7125,3215 v1(7165,3255)
BO_29: P3.34 R31_U_logic_D.11 | length 4537.9
  Top Layer w15: R31_U_logic_D.11@4776.46,2570 v1(4887,2570)
  MidLayer1 w15: v1(7220,3205) 7615,3205 7875,3465 7875,4240 7910,4275 P3.34@8152,4275
  Bottom Layer w15: v1(4887,2570) 5375,2570 5415,2610 5760,2955 6483.67,2955 6543,3014.33 6543,3018 6705,3180 7195,3180 v1(7220,3205)
BO_30: P3.35 R31_U_logic_D.10 | length 4444.4
  Top Layer w15: R31_U_logic_D.10@4776.46,2520 v1(4887,2520)
  MidLayer1 w15: v1(7240,3160) 7630,3160 7920,3450 7920,4110 7977,4167 P3.35@8152,4167
  Bottom Layer w15: v1(4887,2520) 5370,2520 5775,2925 6520,2925 6725,3130 7210,3130 v1(7240,3160)
BO_31: P3.36 R31_U_logic_D.9 | length 4385.2
  Top Layer w15: R31_U_logic_D.9@4776.46,2470 v1(4887,2470)
  MidLayer1 w15: v1(7280,3120) 7645,3120 7955,3430 7955,4030 7984,4059 P3.36@8152,4059
  Bottom Layer w15: v1(4887,2470) 5360,2470 5775,2885 6530,2885 6735,3090 7250,3090 v1(7280,3120)
C1: U8_24dB_c.1 U8_24dB_c.9 U13_U_logic_C.19 U14_U_logic_C.1 | length 1893.9
  Top Layer w12: U8_24dB_c.9@2443.78,4442.36 2443.95,4442.53 2477.87,4442.53 2487.34,4452 2572.86,4452 2584.86,4440 v1(2590,4440) ; v1(2605,4263.23) U8_24dB_c.1@2666.22,4263.23
  Top Layer w15: v1(2605,4263.23) 2605,4220 2800,4025 ; U13_U_logic_C.19@2800,3951.1 2800,4025 ; U14_U_logic_C.1@3715,3867.36 3715,4025 3690,4050 2825,4050 2800,4025
  MidLayer1 w12: v1(2590,4440) 2615,4415 2615,4278.37 2605,4268.37 v1(2605,4263.23)
C2: U8_12dB_c.1 U8_12dB_c.9 U13_U_logic_C.18 U14_U_logic_C.16 | length 2810.4
  Top Layer w12: U8_12dB_c.9@3413.78,4442.36 3413.95,4442.53 3447.87,4442.53 3457.34,4452 3542.86,4452 3554.86,4440 v1(3560,4440) ; v1(3575,4263.23) U8_12dB_c.1@3636.22,4263.23
  Top Layer w15: U13_U_logic_C.18@2850,3951.1 v1(2850,3830) 2850,3770 2920,3700 3210,3700 3255,3655 3255,3570 3285,3540 3700,3540 3715,3555 U14_U_logic_C.16@3715,3662.64
  MidLayer1 w12: v1(3560,4440) 3585,4415 3585,4278.37 3575,4268.37 v1(3575,4263.23)
  MidLayer1 w15: v1(2850,3830) 2850,4160 2940,4250 3561.77,4250 v1(3575,4263.23)
C3: U8_6dB_c.1 U8_6dB_c.9 U13_U_logic_C.17 U14_U_logic_C.9 | length 3076.7
  Top Layer w12: U8_6dB_c.9@4383.78,4442.36 4383.95,4442.53 4417.87,4442.53 4427.34,4452 4512.86,4452 4524.86,4440 v1(4530,4440) ; v1(4545,4263.23) U8_6dB_c.1@4606.22,4263.23
  Top Layer w15: U13_U_logic_C.17@2900,3951.1 v1(2900,3860) 2900,3770 2935,3735 3220,3735 3292.36,3662.64 U14_U_logic_C.9@3365,3662.64
  MidLayer1 w12: v1(4530,4440) 4555,4415 4555,4278.37 4545,4268.37 v1(4545,4263.23)
  MidLayer1 w15: v1(2900,3860) 2900,4145 2965,4210 3541.33,4210 3542.33,4211 4491,4211 v1@4544.11,4264.11
C4: U8_3dB_c.1 U8_3dB_c.9 U13_U_logic_C.16 U14_U_logic_C.8 | length 4042.8
  Top Layer w12: U8_3dB_c.9@5353.78,4442.36 5353.95,4442.53 5387.87,4442.53 5397.34,4452 5482.86,4452 5494.86,4440 v1(5500,4440) ; v1(5515,4263.23) U8_3dB_c.1@5576.22,4263.23
  Top Layer w15: v1(2950,3830) U13_U_logic_C.16@2950,3951.1 2950,4015 2960,4025 3350,4025 3365,4010 U14_U_logic_C.8@3365,3867.36
  MidLayer1 w12: v1(5500,4440) 5525,4415 5525,4278.37 5515,4268.37 v1(5515,4263.23)
  MidLayer1 w15: v1(2950,3830) 2950,4065 2970,4085 5336.77,4085 v1(5515,4263.23)
C5: U2_PZ1_c.1 U2_PZ1_c.9 U13_U_logic_C.15 U15_U_logic_C.1 | length 5315.9
  Top Layer w12: v1(5530,4040) 5675.43,3894.57 U2_PZ1_c.1@5773.78,3894.57 ; v1(5900,3695) 5920.43,3715.43 U2_PZ1_c.9@5996.22,3715.43
  Top Layer w15: v1(3000,3860) U13_U_logic_C.15@3000,3951.1 ; U15_U_logic_C.1@4205,3867.36 v1(4205,3940)
  MidLayer1 w15: v1(3000,3860) 3000,4030 3030,4060 5513.21,4060 5530,4043.21 v1(5530,4040) 5755,3815 5845,3815 5870,3790 5870,3725 v1(5900,3695)
  Bottom Layer w15: v1(3000,3860) 3000,4015 3035,4050 4180,4050 4205,4025 v1(4205,3940)
C6: U2_PZ2_c.1 U2_PZ2_c.9 U13_U_logic_C.14 U15_U_logic_C.16 | length 6484.8
  Top Layer w12: v1(6535,3895) 6535.43,3894.57 U2_PZ2_c.1@6608.78,3894.57 ; v1(6735,3695) 6755.43,3715.43 U2_PZ2_c.9@6831.22,3715.43
  Top Layer w15: v1(3050,3830) U13_U_logic_C.14@3050,3951.1 ; U15_U_logic_C.16@4205,3662.64 4227.64,3662.64 4250,3685 v1(4250,3900)
  MidLayer1 w15: v1(3050,3830) 3050,3990 3075,4015 5465,4015 5625,3855 5625,3710 5745,3590 6630,3590 v1(6735,3695) 6705,3725 6705,3790 6680,3815 6615,3815 v1(6535,3895)
  Bottom Layer w15: v1(3050,3830) 3050,4005 3070,4025 4055,4025 4180,3900 v1(4250,3900)
C7: U2_PZ3_c.1 U2_PZ3_c.9 U13_U_logic_C.13 U15_U_logic_C.9 | length 6609.5
  Top Layer w12: v1(7370,3895) 7370.43,3894.57 U2_PZ3_c.1@7443.78,3894.57 ; v1(7570,3695) 7590.43,3715.43 U2_PZ3_c.9@7666.22,3715.43
  Top Layer w15: v1(3100,3860) U13_U_logic_C.13@3100,3951.1 ; v1(3810,3910) 3810,3805 3855,3760 U15_U_logic_C.9@3855,3662.64
  MidLayer1 w15: v1(3100,3860) 3100,3945 3130,3975 5450,3975 5585,3840 5585,3690 5720,3555 7430,3555 v1(7570,3695) 7540,3725 7540,3790 7515,3815 7450,3815 v1(7370,3895)
  Bottom Layer w15: v1(3100,3860) 3100,3970 3125,3995 3725,3995 v1(3810,3910)
D1: U8_24dB_d.1 U8_24dB_d.9 U13_U_logic_D.19 U14_U_logic_D.1 | length 1918.9
  Top Layer w12: U8_24dB_d.9@2443.78,3347.36 2443.95,3347.53 2477.87,3347.53 2487.34,3357 2572.86,3357 2584.86,3345 v1(2590,3345) ; v1(2605,3168.23) U8_24dB_d.1@2666.22,3168.23
  Top Layer w15: v1(2605,3168.23) 2605,3100 2800,2905 ; U13_U_logic_D.19@2800,2831.1 2800,2905 ; U14_U_logic_D.1@3715,2747.36 3715,2905 3690,2930 2825,2930 2800,2905
  MidLayer1 w12: v1(2590,3345) 2615,3320 2615,3183.37 2605,3173.37 v1(2605,3168.23)
D2: U8_12dB_d.1 U8_12dB_d.9 U13_U_logic_D.18 U14_U_logic_D.16 | length 2851.5
  Top Layer w12: U8_12dB_d.9@3413.78,3347.36 3413.95,3347.53 3447.87,3347.53 3457.34,3357 3542.86,3357 3554.86,3345 v1(3560,3345) ; v1(3575,3168.23) U8_12dB_d.1@3636.22,3168.23
  Top Layer w15: U13_U_logic_D.18@2850,2831.1 v1(2850,2650) 2920,2580 3210,2580 3255,2535 3255,2450 3285,2420 3700,2420 3715,2435 U14_U_logic_D.16@3715,2542.64
  MidLayer1 w12: v1(3560,3345) 3585,3320 3585,3183.37 3575,3173.37 v1(3575,3168.23)
  MidLayer1 w15: v1(2850,2650) 2850,2980 2850,2990 2970,3110 3516.77,3110 v1(3575,3168.23)
D3: U8_6dB_d.1 U8_6dB_d.9 U13_U_logic_D.17 U14_U_logic_D.9 | length 3637
  Top Layer w12: U8_6dB_d.9@4383.78,3347.36 4383.95,3347.53 4417.87,3347.53 4427.34,3357 4512.86,3357 4524.86,3345 v1(4530,3345) ; v1(4545,3168.23) U8_6dB_d.1@4606.22,3168.23
  Top Layer w15: U13_U_logic_D.17@2900,2831.1 v1(2900,2740) 2900,2650 2935,2615 3220,2615 3292.36,2542.64 U14_U_logic_D.9@3365,2542.64
  MidLayer1 w12: v1(4530,3345) 4555,3320 4555,3183.37 4545,3173.37 v1(4545,3168.23)
  MidLayer1 w15: v1@2895,2740 2895,2970 2985,3060 3215,3060 3245,3030 3575,3030 3655,3110 4491.77,3110 ; 3940,3110 4486.77,3110 v1(4545,3168.23)
D4: U8_3dB_d.1 U8_3dB_d.9 U13_U_logic_D.16 U14_U_logic_D.8 | length 4625.8
  Top Layer w12: U8_3dB_d.9@5353.78,3347.36 5353.95,3347.53 5387.87,3347.53 5397.34,3357 5482.86,3357 5494.86,3345 v1(5500,3345) ; v1(5515,3168.23) U8_3dB_d.1@5576.22,3168.23
  Top Layer w15: v1(2950,2710) U13_U_logic_D.16@2950,2831.1 2950,2895 2960,2905 3350,2905 3365,2890 U14_U_logic_D.8@3365,2747.36
  MidLayer1 w12: v1(5500,3345) 5525,3320 5525,3183.37 5515,3173.37 v1(5515,3168.23)
  MidLayer1 w15: v1(2950,2710) 2950,2955 2980,2985 4785,2985 4910,3110 ; 4925,3110 4910,3110 ; 5461.77,3110 5456.77,3110 ; v1(5515,3168.23) 5456.77,3110 ; 4910,3110 5456.77,3110 ; 4910,3110 5456.77,3110
D5: U2_PZ1_d.1 U2_PZ1_d.9 U13_U_logic_D.15 U15_U_logic_D.1 | length 5088.1
  Top Layer w12: v1(5710,2760) 5715.14,2760 5724.71,2769.57 U2_PZ1_d.1@5773.78,2769.57 ; v1(5900,2570) 5920.43,2590.43 U2_PZ1_d.9@5996.22,2590.43
  Top Layer w15: v1(3000,2740) U13_U_logic_D.15@3000,2831.1 ; U15_U_logic_D.1@4205,2747.36 v1(4205,2820)
  MidLayer1 w15: v1(3000,2740) 3000,2910 3040,2950 5520,2950 v1(5710,2760) 5780,2690 5845,2690 5870,2665 5870,2600 v1(5900,2570)
  Bottom Layer w15: v1(3000,2740) 3000,2895 3035,2930 4180,2930 4205,2905 v1(4205,2820)
D6: U2_PZ2_d.1 U2_PZ2_d.9 U13_U_logic_D.14 U15_U_logic_D.16 | length 7442.2
  Top Layer w12: v1(6535,2770) 6535.43,2769.57 U2_PZ2_d.1@6608.78,2769.57 ; v1(6735,2570) 6755.43,2590.43 U2_PZ2_d.9@6831.22,2590.43
  Top Layer w15: v1(3050,2710) U13_U_logic_D.14@3050,2831.1 ; U15_U_logic_D.16@4205,2542.64 4227.64,2542.64 4250,2565 v1(4250,2780)
  MidLayer1 w15: v1(3050,2710) 3050,2860 3095,2905 5510,2905 5615,2800 5615,2590 5735,2470 6590,2470 6650,2530 ; 5760,2460 6625,2460 v1(6735,2570) 6705,2600 6705,2665 6680,2690 6615,2690 v1(6535,2770)
  Bottom Layer w15: v1(3050,2710) 3050,2885 3070,2905 4055,2905 4180,2780 v1(4250,2780)
D7: U2_PZ3_d.1 U2_PZ3_d.9 U13_U_logic_D.13 U15_U_logic_D.9 | length 6672.3
  Top Layer w12: v1(7370,2770) 7370.43,2769.57 U2_PZ3_d.1@7443.78,2769.57 ; v1(7570,2570) 7590.43,2590.43 U2_PZ3_d.9@7666.22,2590.43
  Top Layer w15: v1(3100,2740) U13_U_logic_D.13@3100,2831.1 ; v1(3810,2790) 3810,2685 3855,2640 U15_U_logic_D.9@3855,2542.64
  MidLayer1 w15: v1(3100,2740) 3100,2825 3145,2870 5495,2870 5575,2790 5575,2565 5714.61,2425.38 7380.39,2425.38 ; v1(7370,2770) 7450,2690 7515,2690 7540,2665 7540,2600 v1(7570,2570) 7425,2425 7380,2425
  Bottom Layer w15: v1(3100,2740) 3100,2850 3125,2875 3725,2875 v1(3810,2790)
